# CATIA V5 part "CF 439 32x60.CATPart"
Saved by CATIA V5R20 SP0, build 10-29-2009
Part number: CF 439 32x60
Definition: NONE
Nomenclature: CF 439 32x60
Source: Unknown
Description: CF 439 32x60
Bounding box of the stored display mesh (mm): x -26.5 to 26.5, y 0 to 60, z -26.5 to 26.5
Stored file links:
  C:\Users\Utente\Desktop\IO LAVORO\3D X SITO CF\X SITO\CF 439\CF 439 32x60.CATPart
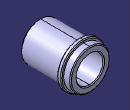
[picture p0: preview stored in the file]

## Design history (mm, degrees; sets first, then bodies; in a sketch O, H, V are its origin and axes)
Body1 "CF 439 32x60" (main body)
  Solid1: solid without history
